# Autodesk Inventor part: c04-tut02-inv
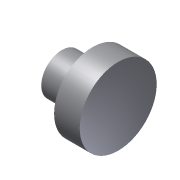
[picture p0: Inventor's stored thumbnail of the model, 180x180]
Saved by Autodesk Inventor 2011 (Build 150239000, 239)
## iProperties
Created: 2010-01
Part Number: c04-tut02-inv
Document SubType Name: Modeling
Designer: CADSoft
Density: 1 g/cm^3
Author: CADSoft
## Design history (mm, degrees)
sketch "Sketch1"
  geometry: L1 (22, 0)-(22, 30); L2 (22, 30)-(2, 30); L3 (2, 30)-(2, 25); L4 (2, 25)-(15.5, 25); L5 (17, 23.5)-(17, 17.5); L6 (15.5, 16)-(-22, 16); L7 (-22, 16)-(-22, 10); L8 (-22, 10)-(-15.5, 10); L9 (-14, 8.5)-(-14, 4); L10 (-14, 4)-(0, 4); L11 (0, 4)-(0, 0); L12 (0, 0)-(22, 0); A1 r 1.5 centre (-15.5, 8.5) between (-14, 8.5) and (-15.5, 10); A2 r 1.5 centre (15.5, 23.5) between (17, 23.5) and (15.5, 25); A3 r 1.5 centre (15.5, 17.5) between (15.5, 16) and (17, 17.5); 2 further points
  constraints: 24 end point, 6 point on circle, 6 tangent, 3 centre point, 2 coincident, 2 equal radius, 2 vertical, 1 horizontal, 1 other
  dimensions: "d0" = 8 diameter of L10 L12; "d1" = 20 diameter of L8 L12; "d2" = 32 diameter of L6 L12; "d3" = 50 diameter of L4 L12; "d5" = 60 diameter of L2 L12; "d6" = 5 distance between parallel lines of L5 L1; "d7" = 20 distance of L1.end L2.end; "d8" = 22 distance of L11.end L1.start; "d9" = 36 distance between parallel lines of L9 L1; "d10" = 44 distance between parallel lines of L7 L1; "d11" = 1.5 radius of A1
revolve "Revolution1" sketch "Sketch1" stored, may be unused: angle "d12" = 90 deg
body "Solid1"
